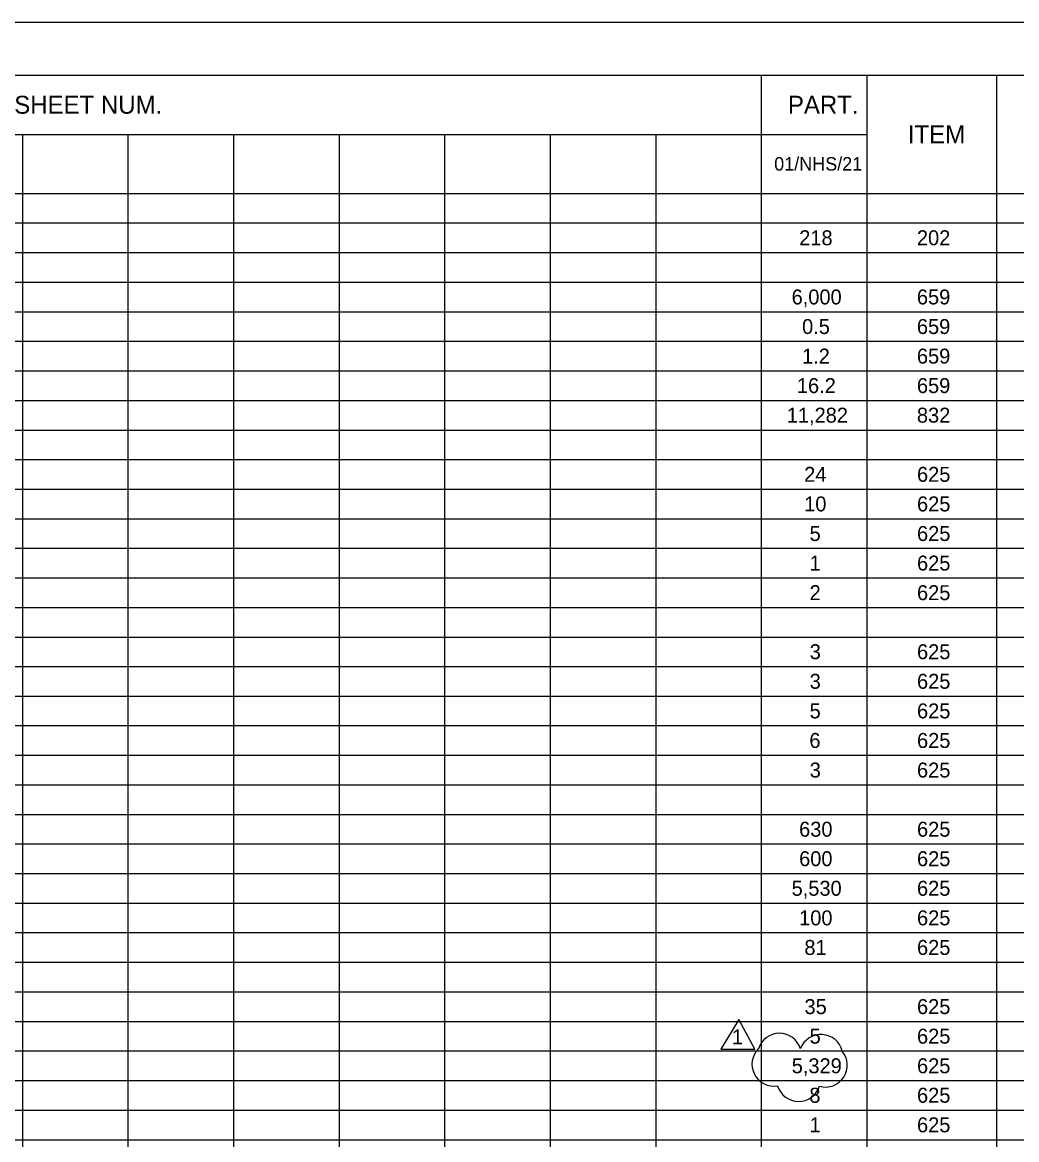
# Model space of a CAD drawing. Extents: x 0 to 34, y 0 to 22.
# Drawn here: x 7.49 to 16.91, y 11.42 to 22 of the extents above; entities that cross this region are included whole.
import ezdxf

# ---------------------------------------------------------------- set-up
doc = ezdxf.new("R2010")
doc.units = 0
for name, color, linetype in [('Default', 7, 'Continuous'), ('SH_Border', 7, 'Continuous'), ('SH_Cut_Line', 7, 'Continuous'), ('SH_Text', 7, 'Continuous')]:
    doc.layers.add(name, color=color, linetype=linetype)

msp = doc.modelspace()

# ---------------------------------------------------------------- linework, layer by layer
at = {"layer": 'Default'}
msp.add_lwpolyline([(14.278, 12.561), (14.107, 12.282), (14.427, 12.28)], close=True, dxfattribs=at)
for centre, start, end in [((14.661, 12.223), 17.5, 162.5), ((15.054, 12.212), 14.1039, 159.1039), ((14.609, 12.138), 134.5743, 279.5743), ((15.095, 12.13), 254.4905, 39.4905), ((14.842, 11.994), 197.0681, 342.0681)]:
    msp.add_arc(centre, 0.208, start, end, dxfattribs=at)
at = {"layer": 'SH_Border'}
msp.add_lwpolyline([(1.5, 21.5), (33.5, 21.5), (33.5, 0.5), (1.5, 0.5)], close=True, dxfattribs=at)
at = {"layer": 'SH_Cut_Line'}
msp.add_lwpolyline([(0, 0), (34, 0), (34, 22), (0, 22)], close=True, dxfattribs=at)
at = {"layer": 'SH_Text'}
for p, q in [((6.496, 21.5), (7.495, 21.5)), ((7.495, 21.5), (8.494, 21.5)), ((8.494, 21.5), (13.49, 21.5)), ((13.49, 21.5), (31.057, 21.5)), ((14.489, 21.5), (14.489, 21.22)), ((15.488, 21.5), (15.488, 21.22)), ((16.715, 21.5), (16.715, 21.22)), ((14.489, 21.22), (14.489, 20.94)), ((15.488, 21.22), (15.488, 20.94)), ((16.715, 21.22), (16.715, 20.94)), ((6.496, 20.94), (7.495, 20.94)), ((7.495, 20.94), (8.494, 20.94)), ((7.495, 20.94), (7.495, 20.66)), ((8.494, 20.94), (13.49, 20.94)), ((8.494, 20.94), (8.494, 20.66)), ((9.493, 20.94), (9.493, 20.66)), ((10.492, 20.94), (10.492, 20.66)), ((11.491, 20.94), (11.491, 20.66)), ((12.49, 20.94), (12.49, 20.66)), ((13.49, 20.94), (15.488, 20.94)), ((13.49, 20.94), (13.49, 20.66)), ((14.489, 20.94), (14.489, 20.66)), ((15.488, 20.94), (15.488, 20.66)), ((16.715, 20.94), (16.715, 20.66)), ((7.495, 20.66), (7.495, 20.38)), ((8.494, 20.66), (8.494, 20.38)), ((9.493, 20.66), (9.493, 20.38)), ((10.492, 20.66), (10.492, 20.38)), ((11.491, 20.66), (11.491, 20.38)), ((12.49, 20.66), (12.49, 20.38)), ((13.49, 20.66), (13.49, 20.38)), ((14.489, 20.66), (14.489, 20.38)), ((15.488, 20.66), (15.488, 20.38)), ((16.715, 20.66), (16.715, 20.38)), ((6.496, 20.38), (7.495, 20.38)), ((7.495, 20.38), (8.494, 20.38)), ((7.495, 20.38), (7.495, 20.101)), ((8.494, 20.38), (13.49, 20.38)), ((8.494, 20.38), (8.494, 20.101)), ((9.493, 20.38), (9.493, 20.101)), ((10.492, 20.38), (10.492, 20.101)), ((11.491, 20.38), (11.491, 20.101)), ((12.49, 20.38), (12.49, 20.101)), ((13.49, 20.38), (31.057, 20.38)), ((13.49, 20.38), (13.49, 20.101)), ((14.489, 20.38), (14.489, 20.101)), ((15.488, 20.38), (15.488, 20.101)), ((16.715, 20.38), (16.715, 20.101)), ((6.496, 20.101), (7.495, 20.101)), ((7.495, 20.101), (8.494, 20.101)), ((7.495, 20.101), (7.495, 18.701)), ((8.494, 20.101), (13.49, 20.101)), ((8.494, 20.101), (8.494, 18.701)), ((9.493, 20.101), (9.493, 18.701)), ((10.492, 20.101), (10.492, 18.701)), ((11.491, 20.101), (11.491, 18.701)), ((12.49, 20.101), (12.49, 18.701)), ((13.49, 20.101), (31.057, 20.101)), ((13.49, 20.101), (13.49, 18.701)), ((14.489, 20.101), (14.489, 18.701)), ((15.488, 20.101), (15.488, 18.701)), ((16.715, 20.101), (16.715, 18.701)), ((6.496, 19.821), (7.495, 19.821)), ((7.495, 19.821), (8.494, 19.821)), ((8.494, 19.821), (13.49, 19.821)), ((13.49, 19.821), (31.057, 19.821)), ((6.496, 19.541), (7.495, 19.541)), ((7.495, 19.541), (8.494, 19.541)), ((8.494, 19.541), (13.49, 19.541)), ((13.49, 19.541), (31.057, 19.541)), ((6.496, 19.261), (7.495, 19.261)), ((7.495, 19.261), (8.494, 19.261)), ((8.494, 19.261), (13.49, 19.261)), ((13.49, 19.261), (31.057, 19.261)), ((6.496, 18.981), (7.495, 18.981)), ((7.495, 18.981), (8.494, 18.981)), ((8.494, 18.981), (13.49, 18.981)), ((13.49, 18.981), (31.057, 18.981)), ((6.496, 18.701), (7.495, 18.701)), ((7.495, 18.701), (8.494, 18.701)), ((7.495, 18.701), (7.495, 18.141)), ((8.494, 18.701), (13.49, 18.701)), ((8.494, 18.701), (8.494, 18.141)), ((9.493, 18.701), (9.493, 18.141)), ((10.492, 18.701), (10.492, 18.141)), ((11.491, 18.701), (11.491, 18.141)), ((12.49, 18.701), (12.49, 18.141)), ((13.49, 18.701), (31.057, 18.701)), ((13.49, 18.701), (13.49, 18.141)), ((14.489, 18.701), (14.489, 18.141)), ((15.488, 18.701), (15.488, 18.141)), ((16.715, 18.701), (16.715, 18.141)), ((6.496, 18.421), (7.495, 18.421)), ((7.495, 18.421), (8.494, 18.421)), ((8.494, 18.421), (13.49, 18.421)), ((13.49, 18.421), (31.057, 18.421)), ((6.496, 18.141), (7.495, 18.141)), ((7.495, 18.141), (8.494, 18.141)), ((7.495, 18.141), (7.495, 17.862)), ((8.494, 18.141), (13.49, 18.141)), ((8.494, 18.141), (8.494, 17.862)), ((9.493, 18.141), (9.493, 17.862)), ((10.492, 18.141), (10.492, 17.862)), ((11.491, 18.141), (11.491, 17.862)), ((12.49, 18.141), (12.49, 17.862)), ((13.49, 18.141), (31.057, 18.141)), ((13.49, 18.141), (13.49, 17.862)), ((14.489, 18.141), (14.489, 17.862)), ((15.488, 18.141), (15.488, 17.862)), ((16.715, 18.141), (16.715, 17.862)), ((6.496, 17.862), (7.495, 17.862)), ((7.495, 17.862), (8.494, 17.862)), ((7.495, 17.862), (7.495, 17.582)), ((8.494, 17.862), (13.49, 17.862)), ((8.494, 17.862), (8.494, 17.582)), ((9.493, 17.862), (9.493, 17.582)), ((10.492, 17.862), (10.492, 17.582)), ((11.491, 17.862), (11.491, 17.582)), ((12.49, 17.862), (12.49, 17.582)), ((13.49, 17.862), (31.057, 17.862)), ((13.49, 17.862), (13.49, 17.582)), ((14.489, 17.862), (14.489, 17.582)), ((15.488, 17.862), (15.488, 17.582)), ((16.715, 17.862), (16.715, 17.582)), ((6.496, 17.582), (7.495, 17.582)), ((7.495, 17.582), (8.494, 17.582)), ((7.495, 17.582), (7.495, 17.302)), ((8.494, 17.582), (13.49, 17.582)), ((8.494, 17.582), (8.494, 17.302)), ((9.493, 17.582), (9.493, 17.302)), ((10.492, 17.582), (10.492, 17.302)), ((11.491, 17.582), (11.491, 17.302)), ((12.49, 17.582), (12.49, 17.302)), ((13.49, 17.582), (31.057, 17.582)), ((13.49, 17.582), (13.49, 17.302)), ((14.489, 17.582), (14.489, 17.302)), ((15.488, 17.582), (15.488, 17.302)), ((16.715, 17.582), (16.715, 17.302)), ((6.496, 17.302), (7.495, 17.302)), ((7.495, 17.302), (8.494, 17.302)), ((7.495, 17.302), (7.495, 17.022)), ((8.494, 17.302), (13.49, 17.302)), ((8.494, 17.302), (8.494, 17.022)), ((9.493, 17.302), (9.493, 17.022)), ((10.492, 17.302), (10.492, 17.022)), ((11.491, 17.302), (11.491, 17.022)), ((12.49, 17.302), (12.49, 17.022)), ((13.49, 17.302), (31.057, 17.302)), ((13.49, 17.302), (13.49, 17.022)), ((14.489, 17.302), (14.489, 17.022)), ((15.488, 17.302), (15.488, 17.022)), ((16.715, 17.302), (16.715, 17.022)), ((6.496, 17.022), (7.495, 17.022)), ((7.495, 17.022), (8.494, 17.022)), ((7.495, 17.022), (7.495, 16.742)), ((8.494, 17.022), (13.49, 17.022)), ((8.494, 17.022), (8.494, 16.742)), ((9.493, 17.022), (9.493, 16.742)), ((10.492, 17.022), (10.492, 16.742)), ((11.491, 17.022), (11.491, 16.742)), ((12.49, 17.022), (12.49, 16.742)), ((13.49, 17.022), (31.057, 17.022)), ((13.49, 17.022), (13.49, 16.742)), ((14.489, 17.022), (14.489, 16.742)), ((15.488, 17.022), (15.488, 16.742)), ((16.715, 17.022), (16.715, 16.742)), ((6.496, 16.742), (7.495, 16.742)), ((7.495, 16.742), (8.494, 16.742)), ((7.495, 16.742), (7.495, 16.182)), ((8.494, 16.742), (13.49, 16.742)), ((8.494, 16.742), (8.494, 16.182)), ((9.493, 16.742), (9.493, 16.182)), ((10.492, 16.742), (10.492, 16.182)), ((11.491, 16.742), (11.491, 16.182)), ((12.49, 16.742), (12.49, 16.182)), ((13.49, 16.742), (31.057, 16.742)), ((13.49, 16.742), (13.49, 16.182)), ((14.489, 16.742), (14.489, 16.182)), ((15.488, 16.742), (15.488, 16.182)), ((16.715, 16.742), (16.715, 16.182)), ((6.496, 16.462), (7.495, 16.462)), ((7.495, 16.462), (8.494, 16.462)), ((8.494, 16.462), (13.49, 16.462)), ((13.49, 16.462), (31.057, 16.462)), ((6.496, 16.182), (7.495, 16.182)), ((7.495, 16.182), (8.494, 16.182)), ((7.495, 16.182), (7.495, 15.902)), ((8.494, 16.182), (13.49, 16.182)), ((8.494, 16.182), (8.494, 15.902)), ((9.493, 16.182), (9.493, 15.902)), ((10.492, 16.182), (10.492, 15.902)), ((11.491, 16.182), (11.491, 15.902)), ((12.49, 16.182), (12.49, 15.902)), ((13.49, 16.182), (31.057, 16.182)), ((13.49, 16.182), (13.49, 15.902)), ((14.489, 16.182), (14.489, 15.902)), ((15.488, 16.182), (15.488, 15.902)), ((16.715, 16.182), (16.715, 15.902)), ((6.496, 15.902), (7.495, 15.902)), ((7.495, 15.902), (8.494, 15.902)), ((7.495, 15.902), (7.495, 15.623)), ((8.494, 15.902), (13.49, 15.902)), ((8.494, 15.902), (8.494, 15.623)), ((9.493, 15.902), (9.493, 15.623)), ((10.492, 15.902), (10.492, 15.623)), ((11.491, 15.902), (11.491, 15.623)), ((12.49, 15.902), (12.49, 15.623)), ((13.49, 15.902), (31.057, 15.902)), ((13.49, 15.902), (13.49, 15.623)), ((14.489, 15.902), (14.489, 15.623)), ((15.488, 15.902), (15.488, 15.623)), ((16.715, 15.902), (16.715, 15.623)), ((6.496, 15.623), (7.495, 15.623)), ((7.495, 15.623), (8.494, 15.623)), ((7.495, 15.623), (7.495, 15.343)), ((8.494, 15.623), (13.49, 15.623)), ((8.494, 15.623), (8.494, 15.343)), ((9.493, 15.623), (9.493, 15.343)), ((10.492, 15.623), (10.492, 15.343)), ((11.491, 15.623), (11.491, 15.343)), ((12.49, 15.623), (12.49, 15.343)), ((13.49, 15.623), (31.057, 15.623)), ((13.49, 15.623), (13.49, 15.343)), ((14.489, 15.623), (14.489, 15.343)), ((15.488, 15.623), (15.488, 15.343)), ((16.715, 15.623), (16.715, 15.343)), ((6.496, 15.343), (7.495, 15.343)), ((7.495, 15.343), (8.494, 15.343)), ((7.495, 15.343), (7.495, 14.783)), ((8.494, 15.343), (13.49, 15.343)), ((8.494, 15.343), (8.494, 14.783)), ((9.493, 15.343), (9.493, 14.783)), ((10.492, 15.343), (10.492, 14.783)), ((11.491, 15.343), (11.491, 14.783)), ((12.49, 15.343), (12.49, 14.783)), ((13.49, 15.343), (31.057, 15.343)), ((13.49, 15.343), (13.49, 14.783)), ((14.489, 15.343), (14.489, 14.783)), ((15.488, 15.343), (15.488, 14.783)), ((16.715, 15.343), (16.715, 14.783)), ((6.496, 15.063), (7.495, 15.063)), ((7.495, 15.063), (8.494, 15.063)), ((8.494, 15.063), (13.49, 15.063)), ((13.49, 15.063), (31.057, 15.063)), ((6.496, 14.783), (7.495, 14.783)), ((7.495, 14.783), (8.494, 14.783)), ((7.495, 14.783), (7.495, 14.503)), ((8.494, 14.783), (13.49, 14.783)), ((8.494, 14.783), (8.494, 14.503)), ((9.493, 14.783), (9.493, 14.503)), ((10.492, 14.783), (10.492, 14.503)), ((11.491, 14.783), (11.491, 14.503)), ((12.49, 14.783), (12.49, 14.503)), ((13.49, 14.783), (31.057, 14.783)), ((13.49, 14.783), (13.49, 14.503)), ((14.489, 14.783), (14.489, 14.503)), ((15.488, 14.783), (15.488, 14.503)), ((16.715, 14.783), (16.715, 14.503)), ((6.496, 14.503), (7.495, 14.503)), ((7.495, 14.503), (8.494, 14.503)), ((7.495, 14.503), (7.495, 14.223)), ((8.494, 14.503), (13.49, 14.503)), ((8.494, 14.503), (8.494, 14.223)), ((9.493, 14.503), (9.493, 14.223)), ((10.492, 14.503), (10.492, 14.223)), ((11.491, 14.503), (11.491, 14.223)), ((12.49, 14.503), (12.49, 14.223)), ((13.49, 14.503), (31.057, 14.503)), ((13.49, 14.503), (13.49, 14.223)), ((14.489, 14.503), (14.489, 14.223)), ((15.488, 14.503), (15.488, 14.223)), ((16.715, 14.503), (16.715, 14.223)), ((6.496, 14.223), (7.495, 14.223)), ((7.495, 14.223), (8.494, 14.223)), ((7.495, 14.223), (7.495, 13.943)), ((8.494, 14.223), (13.49, 14.223)), ((8.494, 14.223), (8.494, 13.943)), ((9.493, 14.223), (9.493, 13.943)), ((10.492, 14.223), (10.492, 13.943)), ((11.491, 14.223), (11.491, 13.943)), ((12.49, 14.223), (12.49, 13.943)), ((13.49, 14.223), (31.057, 14.223)), ((13.49, 14.223), (13.49, 13.943)), ((14.489, 14.223), (14.489, 13.943)), ((15.488, 14.223), (15.488, 13.943)), ((16.715, 14.223), (16.715, 13.943)), ((6.496, 13.943), (7.495, 13.943)), ((7.495, 13.943), (8.494, 13.943)), ((7.495, 13.943), (7.495, 11.704)), ((8.494, 13.943), (13.49, 13.943)), ((8.494, 13.943), (8.494, 11.704)), ((9.493, 13.943), (9.493, 11.704)), ((10.492, 13.943), (10.492, 11.704)), ((11.491, 13.943), (11.491, 11.704)), ((12.49, 13.943), (12.49, 11.704)), ((13.49, 13.943), (31.057, 13.943)), ((13.49, 13.943), (13.49, 11.704)), ((14.489, 13.943), (14.489, 11.704)), ((15.488, 13.943), (15.488, 11.704)), ((16.715, 13.943), (16.715, 11.704)), ((6.496, 13.663), (7.495, 13.663)), ((7.495, 13.663), (8.494, 13.663)), ((8.494, 13.663), (13.49, 13.663)), ((13.49, 13.663), (31.057, 13.663)), ((6.496, 13.384), (7.495, 13.384)), ((7.495, 13.384), (8.494, 13.384)), ((8.494, 13.384), (13.49, 13.384)), ((13.49, 13.384), (31.057, 13.384)), ((6.496, 13.104), (7.495, 13.104)), ((7.495, 13.104), (8.494, 13.104)), ((8.494, 13.104), (13.49, 13.104)), ((13.49, 13.104), (31.057, 13.104)), ((6.496, 12.824), (7.495, 12.824)), ((7.495, 12.824), (8.494, 12.824)), ((8.494, 12.824), (13.49, 12.824)), ((13.49, 12.824), (31.057, 12.824)), ((6.496, 12.544), (7.495, 12.544)), ((7.495, 12.544), (8.494, 12.544)), ((8.494, 12.544), (13.49, 12.544)), ((13.49, 12.544), (31.057, 12.544)), ((6.496, 12.264), (7.495, 12.264)), ((7.495, 12.264), (8.494, 12.264)), ((8.494, 12.264), (13.49, 12.264)), ((13.49, 12.264), (31.057, 12.264)), ((6.496, 11.984), (7.495, 11.984)), ((7.495, 11.984), (8.494, 11.984)), ((8.494, 11.984), (13.49, 11.984)), ((13.49, 11.984), (31.057, 11.984)), ((6.496, 11.704), (7.495, 11.704)), ((7.495, 11.704), (8.494, 11.704)), ((7.495, 11.704), (7.495, 11.424)), ((8.494, 11.704), (13.49, 11.704)), ((8.494, 11.704), (8.494, 11.424)), ((9.493, 11.704), (9.493, 11.424)), ((10.492, 11.704), (10.492, 11.424)), ((11.491, 11.704), (11.491, 11.424)), ((12.49, 11.704), (12.49, 11.424)), ((13.49, 11.704), (31.057, 11.704)), ((13.49, 11.704), (13.49, 11.424)), ((14.489, 11.704), (14.489, 11.424)), ((15.488, 11.704), (15.488, 11.424)), ((16.715, 11.704), (16.715, 11.424)), ((6.496, 11.424), (7.495, 11.424)), ((7.495, 11.424), (8.494, 11.424)), ((7.495, 11.424), (7.495, 10.305)), ((8.494, 11.424), (13.49, 11.424)), ((8.494, 11.424), (8.494, 10.305)), ((9.493, 11.424), (9.493, 10.305)), ((10.492, 11.424), (10.492, 10.305)), ((11.491, 11.424), (11.491, 10.305)), ((12.49, 11.424), (12.49, 10.305)), ((13.49, 11.424), (31.057, 11.424)), ((13.49, 11.424), (13.49, 10.305)), ((14.489, 11.424), (14.489, 10.305)), ((15.488, 11.424), (15.488, 10.305)), ((16.715, 11.424), (16.715, 10.305))]:
    msp.add_line(p, q, dxfattribs=at)

# ---------------------------------------------------------------- texts
at = {"layer": 'Default'}
msp.add_text('1', height=0.14, dxfattribs=at).set_placement((14.211, 12.328))
at = {"layer": 'SH_Text'}
for s, height, p in [('SHEET NUM.', 0.1699, (7.418, 21.135)), ('PART.', 0.1699, (14.741, 21.135)), ('ITEM', 0.1699, (15.876, 20.855)), ('01/NHS/21', 0.1274, (14.611, 20.597)), ('218', 0.1416, (14.848, 19.89)), ('202', 0.1416, (15.962, 19.89)), ('6,000', 0.1416, (14.776, 19.33)), ('659', 0.1416, (15.962, 19.33)), ('0.5', 0.1416, (14.875, 19.05)), ('659', 0.1416, (15.962, 19.05)), ('1.2', 0.1416, (14.875, 18.77)), ('659', 0.1416, (15.962, 18.77)), ('16.2', 0.1416, (14.826, 18.491)), ('659', 0.1416, (15.962, 18.491)), ('11,282', 0.1416, (14.73, 18.211)), ('832', 0.1416, (15.962, 18.211)), ('24', 0.1416, (14.895, 17.651)), ('625', 0.1416, (15.963, 17.651)), ('10', 0.1416, (14.895, 17.371)), ('625', 0.1416, (15.963, 17.371)), ('5', 0.142, (14.946, 17.091)), ('625', 0.1416, (15.963, 17.091)), ('1', 0.142, (14.946, 16.811)), ('625', 0.1416, (15.963, 16.811)), ('2', 0.142, (14.946, 16.531)), ('625', 0.1416, (15.963, 16.531)), ('3', 0.142, (14.947, 15.972)), ('625', 0.1416, (15.963, 15.972)), ('3', 0.142, (14.947, 15.692)), ('625', 0.1416, (15.963, 15.692)), ('5', 0.142, (14.946, 15.412)), ('625', 0.1416, (15.963, 15.412)), ('6', 0.142, (14.944, 15.132)), ('625', 0.1416, (15.963, 15.132)), ('3', 0.142, (14.947, 14.852)), ('625', 0.1416, (15.963, 14.852)), ('630', 0.1416, (14.847, 14.292)), ('625', 0.1416, (15.963, 14.292)), ('600', 0.1416, (14.847, 14.013)), ('625', 0.1416, (15.963, 14.013)), ('5,530', 0.1416, (14.776, 13.733)), ('625', 0.1416, (15.963, 13.733)), ('100', 0.1416, (14.847, 13.453)), ('625', 0.1416, (15.963, 13.453)), ('81', 0.1416, (14.897, 13.173)), ('625', 0.1416, (15.963, 13.173)), ('35', 0.1416, (14.898, 12.613)), ('625', 0.1416, (15.963, 12.613)), ('5', 0.142, (14.946, 12.333)), ('625', 0.1416, (15.963, 12.333)), ('5,329', 0.1416, (14.777, 12.053)), ('625', 0.1416, (15.963, 12.053)), ('8', 0.142, (14.944, 11.774)), ('625', 0.1416, (15.963, 11.774)), ('1', 0.142, (14.946, 11.494)), ('625', 0.1416, (15.963, 11.494))]:
    msp.add_text(s, height=height, dxfattribs=at).set_placement(p)

doc.saveas('drawing.dxf')
